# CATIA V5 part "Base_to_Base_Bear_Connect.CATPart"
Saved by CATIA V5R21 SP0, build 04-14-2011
Part number: Base_to_Base_Bear_Connect
Bounding box of the stored display mesh (mm): x 0 to 8, y -32 to 32, z -25.5 to 25.5
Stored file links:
  F:\教程\Robotic_Arm_Arduino_Kinect\机械臂CAD\Arm_Detailed_Design\Base_to_Base_Bear_Connect.CATPart
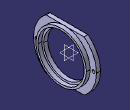
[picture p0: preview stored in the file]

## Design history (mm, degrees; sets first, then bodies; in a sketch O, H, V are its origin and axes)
Body1 (main body)
  Sketch1 on yz-plane, origin (0, 0, 0), H (0, 1, 0), V (0, 0, 1)
    circle A1 centre (0, 0) radius 32
    circle A2 centre (0, 0) radius 21.5
    radius A2 = 21.5
    radius A1 = 32
  Pad1: profile Sketch1, direction (1, 0, 0), length 4
  Sketch2 on end face of Pad1, origin (4, 0, 0), H (0, 1, 0), V (0, 0, 1)
    circle A1 centre (0, 0) radius 23.5
    circle A2 centre (0, 0) radius 25.5
    radius A2 = 25.5
    radius A1 = 23.5
  Pad2: profile Sketch2, direction (1, 0, 0), length 4
  Sketch3 on start face of Pad1, origin (0, 0, 0), H (0, -1, 0), V (0, 0, 1)
    circle A1 centre (29, 0) radius 1.5
    point P1 (29, 0)
    point P2 (30.5, 0)
    circle A2 centre (-29, 0) radius 1.5
    point P3 (-29, 0)
    line L1 (-30.0408, 34.0267) -> (31.4698, 34.0267)
    line L2 (31.4698, 34.0267) -> (31.4698, 25.5)
    line L3 (31.4698, 25.5) -> (-30.0408, 25.5)
    line L4 (-30.0408, 25.5) -> (-30.0408, 34.0267)
    reference projected circle E1 centre (0, 0) radius 25.5 from edge [end face of Pad1 | face of Pad2 from Sketch2.A2]
    line L5 (26.753, -25.5) -> (-25.9884, -25.5)
    line L6 (-25.9884, -25.5) -> (-25.9884, -39.4596)
    line L7 (-25.9884, -39.4596) -> (26.753, -39.4596)
    line L8 (26.753, -39.4596) -> (26.753, -25.5)
    reference projected circle E2 centre (0, 0) radius 25.5 from edge [end face of Pad1 | face of Pad2 from Sketch2.A2]
    radius A1 = 1.5
    radius A2 = 1.5
    distance V P1 = 29
    distance V P3 = 29
    coincidence: P1 H, A1 P2, P2 H, P3 H
    horizontal: L1 H, L3 H, L5 H, L7 H
    vertical: L2 V, L4 V, L6 V, L8 V
    tangency: E1 L3, L5 E2
  Pocket1: profile Sketch3, direction (1, 0, 0), through (limit type 3)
